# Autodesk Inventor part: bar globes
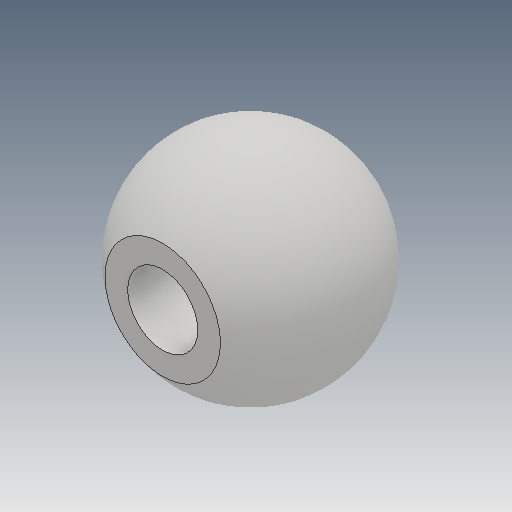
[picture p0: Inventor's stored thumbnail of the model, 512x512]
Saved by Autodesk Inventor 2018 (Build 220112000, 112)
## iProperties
Created: 2016-03
Part Number: bar globes
Material: Generic
Document SubType Name: Modeling
Designer: Sandeep
Density: 1 g/cm^3
Appearance: Default
Author: Sandeep
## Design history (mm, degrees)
sketch "Sketch1"
  geometry: L1 (0, 12)-(0, 0); A1 r 6 centre (0, 6) between (0, 12) and (0, 0)
  constraints: 2 end point, 2 point on circle, 1 centre point, 1 midpoint, 1 vertical
revolve "Revolution1" sketch "Sketch1" stored, may be unused: angle "d1" = 90 deg
sketch "Sketch2"
  geometry: 1 further point
sketch "Sketch3"
  geometry: 1 further point
sketch "Sketch4"
  geometry: 1 further point
sketch "Sketch5"
  geometry: L1 (5.014, 9.295)-(5.014, 2.705); A1 r 6 centre (0, 6) between (0, 0) and (5.014, 9.295) reference; A2 r 6 centre (0, 6) between (0, 0) and (5.014, 2.705) reference; 2 further points
  constraints: 2 end point, 2 point on circle, 1 vertical, 1 vertical alignment
extrude "Extrusion1" cut sketch "Sketch5" stored distance "d2" = 10; taper "d3" = 0 deg
sketch "Sketch6"
  geometry: L1 (5.65, 4.164)-(5.65, -4.091); A1 r 6 centre (0, 0) between (-5.014, -3.295) and (-5.014, 3.295) reference; 1 further point
  constraints: 2 end point, 1 vertical
extrude "Extrusion2" cut sketch "Sketch6" distance "d5" = 15.75; taper "d6" = 0 deg
sketch "Sketch7"
  geometry: L1 (-5.65, 3.981)-(-5.65, 8.019) reference; L2 (-5.65, 6)-(5.014, 6); L3 (-4.986, 8)-(5.014, 8); L4 (5.014, 8)-(5.014, 6); L5 (5.014, 9.295)-(5.014, 2.705) reference; L6 (-5.65, 7.336)-(-5.65, 6); L7 (-4.986, 8)-(-5.65, 7.336); 3 further points
  constraints: 10 end point, 2 collinear, 2 horizontal, 2 midpoint, 2 point on line
  dimensions: "d16" = 4 diameter of L3 L2; "d17" = 10 distance of L3.end L3.start; "d19" = 45 deg angle of L7 L3
revolve "Revolution2" sketch "Sketch7" stored, may be unused: angle "d18" = 90 deg
body "Solid1"
other parameters: "d4" = 15.75
